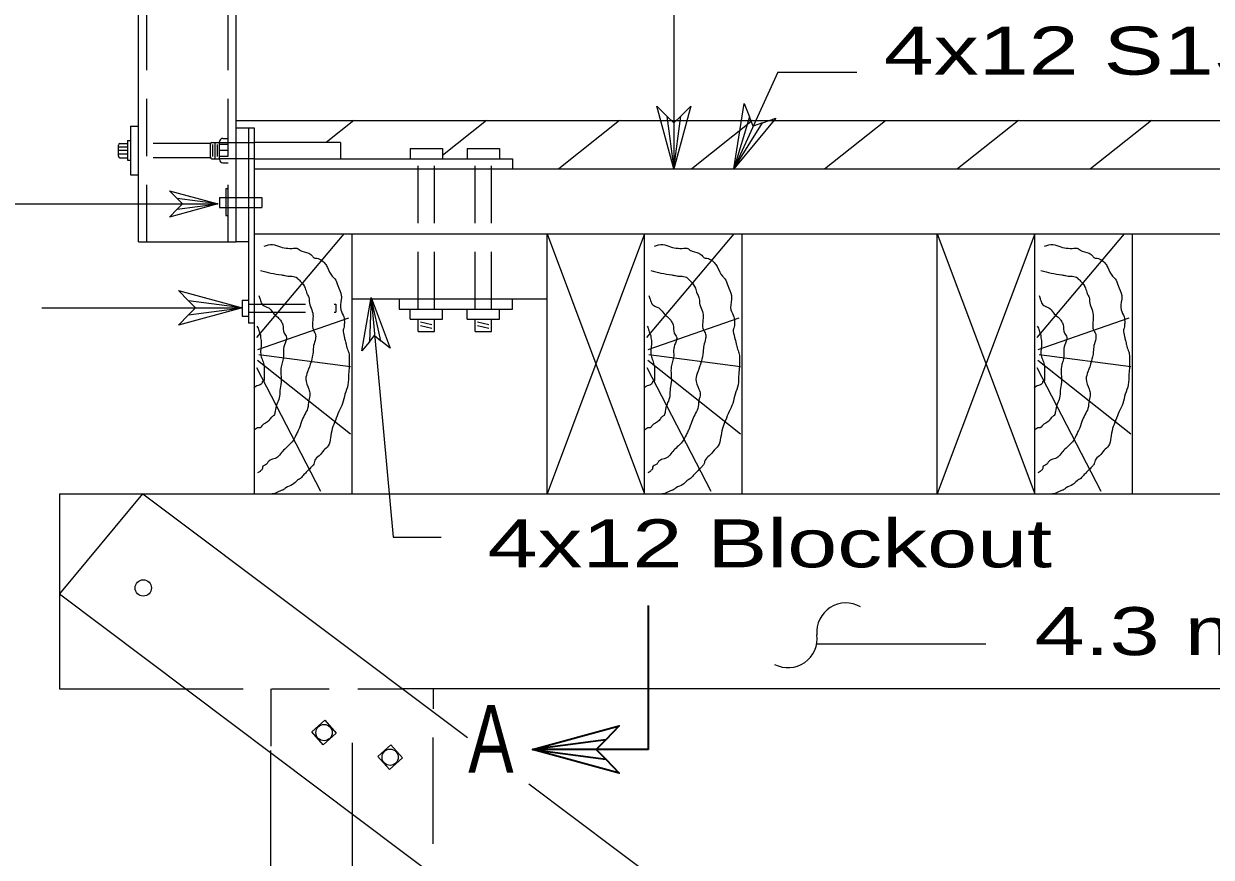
# Model space of a CAD drawing. Extents: x 13426 to 15509, y -9298 to -5111.
# Drawn here: x 15341.75 to 15374.08, y -5520.47 to -5497.78 of the extents above; entities that cross this region are included whole.
import ezdxf
from ezdxf.enums import TextEntityAlignment as Align

# ---------------------------------------------------------------- set-up
doc = ezdxf.new("R2010")
doc.units = 0
doc.header["$LTSCALE"] = 0.52
doc.linetypes.add('MEDIUM_DASHED', pattern=[4.5, 3, -1.5])
for name, color, linetype, lineweight in [('1', 7, 'Continuous', 13), ('15', 7, 'Continuous', 13), ('16', 7, 'Continuous', 25), ('2', 7, 'Continuous', 25), ('20', 7, 'Continuous', 13), ('4', 7, 'Continuous', 13), ('5', 7, 'Continuous', 25)]:
    doc.layers.add(name, color=color, linetype=linetype, lineweight=lineweight)
doc.layers.add('19', color=7, linetype='Continuous')

msp = doc.modelspace()

# ---------------------------------------------------------------- linework, layer by layer
at = {"layer": '1', "lineweight": 25}
for p, q in [((15342.717, -5510.579), (15342.717, -5515.89)), ((15342.717, -5515.89), (15346.162, -5515.89)), ((15417.071, -5515.89), (15352.058, -5515.89)), ((15352.897, -5515.89), (15352.897, -5516.435)), ((15352.897, -5520.11), (15352.897, -5517.212)), ((15348.471, -5573.164), (15348.471, -5517.564))]:
    msp.add_line(p, q, dxfattribs=at)
at = {"layer": '1', "linetype": 'MEDIUM_DASHED', "lineweight": 25}
for p, q in [((15346.162, -5515.89), (15352.058, -5515.89)), ((15348.471, -5515.89), (15348.471, -5517.564))]:
    msp.add_line(p, q, dxfattribs=at)
at = {"layer": '1', "lineweight": 25}
msp.add_lwpolyline([(15342.717, -5510.579), (15417.071, -5510.579), (15417.071, -5515.89)], dxfattribs=at)
at = {"layer": '15'}
for p, q in [((15359.445, -5491.991), (15359.445, -5501.728)), ((15362.274, -5499.093), (15361.077, -5501.728)), ((15362.274, -5499.093), (15364.424, -5499.093)), ((15341.243, -5502.683), (15347.034, -5502.683)), ((15342.24, -5505.514), (15347.695, -5505.51)), ((15363.336, -5514.659), (15367.935, -5514.659)), ((15350.684, -5517.363), (15350.684, -5528.112))]:
    msp.add_line(p, q, dxfattribs=at)
at = {"layer": '15', "lineweight": 35}
for q in [(15358.759, -5513.623), (15355.601, -5517.539)]:
    msp.add_line((15358.759, -5517.539), q, dxfattribs=at)
at = {"layer": '15'}
msp.add_lwpolyline([(15351.203, -5505.231), (15351.806, -5511.755), (15353.111, -5511.755)], dxfattribs=at)
for centre, start, end in [((15364.1313, -5514.3406), 59.84377, 185.31451), ((15362.5553, -5514.5196), 242.17771, 7.64844)]:
    msp.add_arc(centre, 0.7933, start, end, dxfattribs=at)
at = {"layer": '16'}
for points in [[(15359.633, -5500.289), (15359.91, -5500.024), (15359.445, -5501.728), (15358.98, -5500.024), (15359.257, -5500.289), (15359.445, -5501.728), (15359.633, -5500.289), (15359.445, -5500.477), (15359.257, -5500.289)], [(15361.857, -5500.473), (15362.225, -5500.344), (15361.077, -5501.728), (15361.364, -5499.952), (15361.508, -5500.315), (15361.077, -5501.728), (15361.857, -5500.473), (15361.603, -5500.568), (15361.508, -5500.315)], [(15345.921, -5502.537), (15345.715, -5502.323), (15347.034, -5502.683), (15345.715, -5503.042), (15345.921, -5502.828), (15347.034, -5502.683), (15345.921, -5502.537), (15346.066, -5502.683), (15345.921, -5502.828)], [(15346.23, -5505.32), (15345.96, -5505.038), (15347.695, -5505.51), (15345.961, -5505.984), (15346.231, -5505.703), (15347.695, -5505.51), (15346.23, -5505.32), (15346.422, -5505.511), (15346.231, -5505.703)], [(15351.157, -5506.438), (15350.948, -5506.68), (15351.203, -5505.231), (15351.72, -5506.609), (15351.469, -5506.41), (15351.203, -5505.231), (15351.157, -5506.438), (15351.299, -5506.268), (15351.469, -5506.41)]]:
    msp.add_lwpolyline(points, dxfattribs=at)
at = {"layer": '16', "lineweight": 35}
msp.add_lwpolyline([(15357.592, -5517.799), (15357.959, -5518.182), (15355.601, -5517.539), (15357.959, -5516.896), (15357.592, -5517.279), (15355.601, -5517.539), (15357.592, -5517.799), (15357.332, -5517.539), (15357.592, -5517.279)], dxfattribs=at)
at = {"layer": '2'}
for p, q in [((15352.266, -5501.174), (15353.151, -5501.174)), ((15352.266, -5501.174), (15352.266, -5501.451)), ((15353.151, -5501.174), (15353.151, -5501.451)), ((15353.815, -5501.174), (15354.7, -5501.174)), ((15353.815, -5501.174), (15353.815, -5501.451)), ((15354.7, -5501.174), (15354.7, -5501.451)), ((15347.246, -5502.267), (15347.246, -5502.998)), ((15347.246, -5502.267), (15347.303, -5502.267)), ((15347.074, -5502.511), (15347.074, -5502.781)), ((15347.074, -5502.511), (15347.241, -5502.511)), ((15347.074, -5502.781), (15347.241, -5502.781)), ((15347.246, -5502.998), (15347.303, -5502.998)), ((15347.695, -5505.301), (15347.862, -5505.301)), ((15347.695, -5505.301), (15347.695, -5505.744)), ((15352.266, -5505.821), (15352.266, -5505.545)), ((15353.151, -5505.821), (15353.151, -5505.545)), ((15353.815, -5505.821), (15353.815, -5505.545)), ((15354.7, -5505.821), (15354.7, -5505.545)), ((15347.695, -5505.744), (15347.862, -5505.744)), ((15352.266, -5505.821), (15353.151, -5505.821)), ((15352.487, -5506.153), (15352.487, -5505.821)), ((15352.55, -5505.992), (15352.858, -5506.069)), ((15352.552, -5505.89), (15352.86, -5505.966)), ((15352.93, -5506.153), (15352.93, -5505.821)), ((15353.815, -5505.821), (15354.7, -5505.821)), ((15354.036, -5506.153), (15354.036, -5505.821)), ((15354.099, -5505.992), (15354.407, -5506.069)), ((15354.101, -5505.89), (15354.409, -5505.966)), ((15354.479, -5506.153), (15354.479, -5505.821)), ((15352.487, -5506.153), (15352.93, -5506.153)), ((15354.036, -5506.153), (15354.479, -5506.153)), ((15344.983, -5510.579), (15342.719, -5513.305)), ((15344.986, -5510.579), (15353.824, -5517.216)), ((15342.719, -5513.305), (15414.878, -5567.491)), ((15355.496, -5518.472), (15417.071, -5564.711))]:
    msp.add_line(p, q, dxfattribs=at)
at = {"layer": '2', "linetype": 'MEDIUM_DASHED'}
for p, q in [((15352.487, -5505.545), (15352.487, -5501.451)), ((15352.93, -5505.545), (15352.93, -5501.451)), ((15354.036, -5505.545), (15354.036, -5501.451)), ((15354.479, -5505.545), (15354.479, -5501.451)), ((15347.241, -5502.511), (15348.226, -5502.511)), ((15347.241, -5502.781), (15348.226, -5502.781)), ((15348.226, -5502.511), (15348.226, -5502.781)), ((15347.862, -5505.633), (15350.241, -5505.633))]:
    msp.add_line(p, q, dxfattribs=at)
msp.add_lwpolyline([(15347.862, -5505.412), (15350.241, -5505.412), (15350.241, -5505.633)], dxfattribs=at)
at = {"layer": '2'}
for points in [[(15349.589, -5517.059), (15349.943, -5516.745), (15350.257, -5517.098), (15349.902, -5517.413)], [(15351.388, -5517.731), (15351.742, -5517.417), (15352.056, -5517.77), (15351.702, -5518.084)]]:
    msp.add_lwpolyline(points, close=True, dxfattribs=at)
for centre in [(15345.0015, -5513.1405), (15349.923, -5517.0797), (15351.7222, -5517.7512)]:
    msp.add_circle(centre, 0.2213, dxfattribs=at)
at = {"layer": '4', "lineweight": 25}
for p, q in [((15347.53, -5500.409), (15412.258, -5500.409)), ((15350.73, -5500.409), (15349.977, -5501.008)), ((15354.349, -5500.409), (15353.151, -5501.362)), ((15357.968, -5500.409), (15356.312, -5501.728)), ((15361.588, -5500.409), (15359.931, -5501.728)), ((15363.55, -5501.728), (15365.207, -5500.409)), ((15368.826, -5500.409), (15367.17, -5501.728)), ((15372.446, -5500.409), (15370.789, -5501.728)), ((15348.028, -5501.451), (15355.049, -5501.451)), ((15355.049, -5501.451), (15355.049, -5501.728)), ((15348.028, -5501.728), (15411.76, -5501.728)), ((15348.028, -5510.579), (15348.028, -5501.728)), ((15348.028, -5503.498), (15411.76, -5503.498)), ((15350.684, -5510.579), (15350.684, -5503.498)), ((15355.995, -5510.579), (15355.995, -5503.498)), ((15355.995, -5503.498), (15358.65, -5510.579)), ((15358.65, -5503.498), (15355.995, -5510.579)), ((15358.65, -5510.579), (15358.65, -5503.498)), ((15361.305, -5510.579), (15361.305, -5503.498)), ((15366.617, -5510.579), (15366.617, -5503.498)), ((15366.617, -5503.498), (15369.272, -5510.579)), ((15369.272, -5503.498), (15366.617, -5510.579)), ((15369.272, -5510.579), (15369.272, -5503.498)), ((15371.928, -5510.579), (15371.928, -5503.498)), ((15350.684, -5505.268), (15355.995, -5505.268)), ((15351.968, -5505.268), (15351.968, -5505.545)), ((15355.049, -5505.545), (15355.049, -5505.268)), ((15351.968, -5505.545), (15355.049, -5505.545))]:
    msp.add_line(p, q, dxfattribs=at)
at = {"layer": '4'}
for p, q in [((15344.653, -5500.567), (15344.875, -5500.567)), ((15344.653, -5500.567), (15344.653, -5501.895)), ((15344.323, -5501.38), (15344.323, -5501.081)), ((15344.571, -5501.134), (15344.323, -5501.134)), ((15344.367, -5501.037), (15344.571, -5501.037)), ((15344.571, -5500.954), (15344.571, -5501.495)), ((15344.571, -5500.954), (15344.653, -5500.954)), ((15346.828, -5501.407), (15346.828, -5501.052)), ((15346.872, -5501.008), (15347.077, -5501.008)), ((15346.889, -5501.064), (15346.889, -5501.395)), ((15346.953, -5501.008), (15346.953, -5501.451)), ((15347.016, -5501.064), (15347.016, -5501.395)), ((15347.077, -5501.472), (15347.077, -5500.987)), ((15347.309, -5501.064), (15347.077, -5501.064)), ((15347.166, -5500.898), (15347.309, -5500.898)), ((15350.368, -5501.008), (15348.028, -5501.008)), ((15350.368, -5501.008), (15350.368, -5501.451)), ((15344.571, -5501.231), (15344.323, -5501.231)), ((15344.571, -5501.328), (15344.323, -5501.328)), ((15344.367, -5501.425), (15344.571, -5501.425)), ((15344.571, -5501.495), (15344.653, -5501.495)), ((15346.872, -5501.451), (15347.077, -5501.451)), ((15347.309, -5501.229), (15347.077, -5501.229)), ((15347.309, -5501.395), (15347.077, -5501.395)), ((15347.166, -5501.56), (15347.309, -5501.56)), ((15344.653, -5501.895), (15344.875, -5501.895)), ((15350.459, -5503.497), (15348.081, -5506.317)), ((15361.081, -5503.497), (15358.702, -5506.317)), ((15371.703, -5503.497), (15369.325, -5506.317)), ((15350.59, -5505.79), (15348.113, -5506.657)), ((15361.212, -5505.79), (15358.735, -5506.657)), ((15371.834, -5505.79), (15369.357, -5506.657)), ((15350.639, -5508.951), (15348.113, -5506.946)), ((15350.639, -5507.116), (15348.146, -5506.793)), ((15361.262, -5508.951), (15358.735, -5506.946)), ((15361.262, -5507.116), (15358.768, -5506.793)), ((15371.884, -5508.951), (15369.357, -5506.946)), ((15371.884, -5507.116), (15369.39, -5506.793)), ((15349.836, -5510.514), (15348.097, -5507.15)), ((15360.458, -5510.514), (15358.719, -5507.15)), ((15371.08, -5510.514), (15369.341, -5507.15))]:
    msp.add_line(p, q, dxfattribs=at)
at = {"layer": '4', "linetype": 'MEDIUM_DASHED'}
for p, q in [((15346.83, -5501.037), (15344.571, -5501.037)), ((15347.077, -5501.008), (15348.028, -5501.008)), ((15346.83, -5501.425), (15344.571, -5501.425)), ((15348.028, -5501.451), (15347.077, -5501.451))]:
    msp.add_line(p, q, dxfattribs=at)
at = {"layer": '4'}
for centre, radius, start, end in [((15344.3669, -5501.0814), 0.0443, 90, 179.99999), ((15346.8718, -5501.0524), 0.0443, 90, 179.99999), ((15347.1659, -5500.987), 0.0885, 90, 179.99999), ((15344.3669, -5501.3801), 0.0443, 180, 269.99999), ((15346.8718, -5501.4065), 0.0443, 180, 269.99999), ((15347.1659, -5501.4719), 0.0885, 180, 269.99999)]:
    msp.add_arc(centre, radius, start, end, dxfattribs=at)
for points in [[(15348.294, -5503.837), (15348.523, -5503.786), (15348.737, -5503.854), (15349.147, -5503.888), (15349.18, -5503.888), (15349.262, -5503.939), (15349.508, -5504.024), (15349.606, -5504.108), (15349.672, -5504.159), (15349.688, -5504.159), (15349.951, -5504.312), (15350.016, -5504.414), (15350.148, -5504.652), (15350.213, -5504.72), (15350.295, -5504.907), (15350.393, -5505.179), (15350.393, -5505.281), (15350.377, -5505.57), (15350.459, -5505.756), (15350.475, -5505.926), (15350.459, -5506.062), (15350.442, -5506.113), (15350.442, -5506.164), (15350.459, -5506.232), (15350.475, -5506.317), (15350.508, -5506.436), (15350.525, -5506.521), (15350.574, -5506.674), (15350.607, -5506.81), (15350.607, -5506.929), (15350.607, -5507.116), (15350.59, -5507.32), (15350.574, -5507.608), (15350.492, -5507.863), (15350.426, -5508.118), (15350.328, -5508.339), (15350.23, -5508.577), (15350.148, -5508.798), (15350.098, -5509.052), (15350.033, -5509.273), (15349.917, -5509.392), (15349.787, -5509.545), (15349.672, -5509.664), (15349.655, -5509.732), (15349.623, -5509.8), (15349.557, -5509.868), (15349.458, -5509.97), (15349.376, -5510.055), (15349.278, -5510.157), (15349.18, -5510.225), (15349.065, -5510.327), (15348.884, -5510.412), (15348.819, -5510.463), (15348.737, -5510.497), (15348.655, -5510.53), (15348.507, -5510.582), (15348.506, -5510.582)], [(15358.916, -5503.837), (15359.145, -5503.786), (15359.359, -5503.854), (15359.769, -5503.888), (15359.802, -5503.888), (15359.884, -5503.939), (15360.129, -5504.024), (15360.228, -5504.108), (15360.294, -5504.159), (15360.31, -5504.159), (15360.572, -5504.312), (15360.638, -5504.414), (15360.769, -5504.652), (15360.835, -5504.72), (15360.917, -5504.907), (15361.015, -5505.179), (15361.015, -5505.281), (15360.999, -5505.57), (15361.081, -5505.756), (15361.097, -5505.926), (15361.081, -5506.062), (15361.065, -5506.113), (15361.065, -5506.164), (15361.081, -5506.232), (15361.097, -5506.317), (15361.13, -5506.436), (15361.147, -5506.521), (15361.196, -5506.674), (15361.229, -5506.81), (15361.229, -5506.929), (15361.229, -5507.116), (15361.212, -5507.32), (15361.196, -5507.608), (15361.114, -5507.863), (15361.048, -5508.118), (15360.95, -5508.339), (15360.851, -5508.577), (15360.769, -5508.798), (15360.72, -5509.052), (15360.654, -5509.273), (15360.54, -5509.392), (15360.408, -5509.545), (15360.294, -5509.664), (15360.277, -5509.732), (15360.244, -5509.8), (15360.179, -5509.868), (15360.081, -5509.97), (15359.999, -5510.055), (15359.9, -5510.157), (15359.802, -5510.225), (15359.687, -5510.327), (15359.506, -5510.412), (15359.441, -5510.463), (15359.359, -5510.497), (15359.277, -5510.53), (15359.129, -5510.582), (15359.128, -5510.582)], [(15369.538, -5503.837), (15369.768, -5503.786), (15369.98, -5503.854), (15370.391, -5503.888), (15370.423, -5503.888), (15370.506, -5503.939), (15370.752, -5504.024), (15370.85, -5504.108), (15370.916, -5504.159), (15370.932, -5504.159), (15371.195, -5504.312), (15371.26, -5504.414), (15371.391, -5504.652), (15371.457, -5504.72), (15371.539, -5504.907), (15371.638, -5505.179), (15371.638, -5505.281), (15371.621, -5505.57), (15371.703, -5505.756), (15371.72, -5505.926), (15371.703, -5506.062), (15371.687, -5506.113), (15371.687, -5506.164), (15371.703, -5506.232), (15371.72, -5506.317), (15371.752, -5506.436), (15371.768, -5506.521), (15371.818, -5506.674), (15371.85, -5506.81), (15371.85, -5506.929), (15371.85, -5507.116), (15371.834, -5507.32), (15371.818, -5507.608), (15371.736, -5507.863), (15371.67, -5508.118), (15371.572, -5508.339), (15371.473, -5508.577), (15371.391, -5508.798), (15371.342, -5509.052), (15371.277, -5509.273), (15371.162, -5509.392), (15371.031, -5509.545), (15370.916, -5509.664), (15370.899, -5509.732), (15370.866, -5509.8), (15370.801, -5509.868), (15370.702, -5509.97), (15370.62, -5510.055), (15370.522, -5510.157), (15370.423, -5510.225), (15370.309, -5510.327), (15370.128, -5510.412), (15370.063, -5510.463), (15369.98, -5510.497), (15369.898, -5510.53), (15369.751, -5510.582), (15369.75, -5510.582)], [(15348.195, -5504.499), (15348.474, -5504.567), (15348.769, -5504.618), (15348.868, -5504.635), (15348.999, -5504.652), (15349.048, -5504.652), (15349.196, -5504.703), (15349.212, -5504.72), (15349.294, -5504.805), (15349.409, -5504.975), (15349.458, -5505.128), (15349.508, -5505.23), (15349.524, -5505.383), (15349.59, -5505.57), (15349.623, -5505.739), (15349.606, -5505.96), (15349.623, -5506.096), (15349.688, -5506.232), (15349.688, -5506.351), (15349.639, -5506.538), (15349.623, -5506.708), (15349.475, -5507.251), (15349.426, -5507.455), (15349.508, -5507.727), (15349.54, -5507.863), (15349.508, -5508.033), (15349.475, -5508.254), (15349.393, -5508.424), (15349.311, -5508.611), (15349.229, -5508.832), (15349.18, -5508.933), (15349.081, -5509.121), (15348.95, -5509.273), (15348.819, -5509.392), (15348.589, -5509.613), (15348.523, -5509.63), (15348.458, -5509.664), (15348.408, -5509.698), (15348.359, -5509.766), (15348.244, -5509.851), (15348.244, -5509.885), (15348.195, -5509.953), (15348.179, -5509.97), (15348.113, -5510.004)], [(15358.817, -5504.499), (15359.096, -5504.567), (15359.391, -5504.618), (15359.49, -5504.635), (15359.621, -5504.652), (15359.67, -5504.652), (15359.818, -5504.703), (15359.834, -5504.72), (15359.917, -5504.805), (15360.031, -5504.975), (15360.081, -5505.128), (15360.129, -5505.23), (15360.146, -5505.383), (15360.212, -5505.57), (15360.244, -5505.739), (15360.228, -5505.96), (15360.244, -5506.096), (15360.31, -5506.232), (15360.31, -5506.351), (15360.261, -5506.538), (15360.244, -5506.708), (15360.097, -5507.251), (15360.047, -5507.455), (15360.129, -5507.727), (15360.162, -5507.863), (15360.129, -5508.033), (15360.097, -5508.254), (15360.015, -5508.424), (15359.933, -5508.611), (15359.851, -5508.832), (15359.802, -5508.933), (15359.703, -5509.121), (15359.572, -5509.273), (15359.441, -5509.392), (15359.211, -5509.613), (15359.145, -5509.63), (15359.08, -5509.664), (15359.031, -5509.698), (15358.981, -5509.766), (15358.867, -5509.851), (15358.867, -5509.885), (15358.817, -5509.953), (15358.801, -5509.97), (15358.735, -5510.004)], [(15369.439, -5504.499), (15369.718, -5504.567), (15370.013, -5504.618), (15370.112, -5504.635), (15370.243, -5504.652), (15370.292, -5504.652), (15370.44, -5504.703), (15370.456, -5504.72), (15370.538, -5504.805), (15370.653, -5504.975), (15370.702, -5505.128), (15370.752, -5505.23), (15370.768, -5505.383), (15370.834, -5505.57), (15370.866, -5505.739), (15370.85, -5505.96), (15370.866, -5506.096), (15370.932, -5506.232), (15370.932, -5506.351), (15370.883, -5506.538), (15370.866, -5506.708), (15370.719, -5507.251), (15370.67, -5507.455), (15370.752, -5507.727), (15370.784, -5507.863), (15370.752, -5508.033), (15370.719, -5508.254), (15370.637, -5508.424), (15370.555, -5508.611), (15370.473, -5508.832), (15370.423, -5508.933), (15370.325, -5509.121), (15370.194, -5509.273), (15370.063, -5509.392), (15369.833, -5509.613), (15369.768, -5509.63), (15369.702, -5509.664), (15369.653, -5509.698), (15369.604, -5509.766), (15369.489, -5509.851), (15369.489, -5509.885), (15369.439, -5509.953), (15369.423, -5509.97), (15369.357, -5510.004)], [(15348.146, -5505.179), (15348.179, -5505.281), (15348.228, -5505.4), (15348.343, -5505.485), (15348.392, -5505.502), (15348.474, -5505.57), (15348.589, -5505.705), (15348.687, -5505.79), (15348.753, -5505.875), (15348.802, -5505.978), (15348.835, -5506.198), (15348.901, -5506.317), (15348.884, -5506.419), (15348.819, -5506.623), (15348.819, -5506.827), (15348.753, -5507.116), (15348.753, -5507.541), (15348.72, -5507.761), (15348.704, -5507.965), (15348.638, -5508.135), (15348.589, -5508.339), (15348.556, -5508.441), (15348.49, -5508.492), (15348.425, -5508.577), (15348.228, -5508.73), (15348.179, -5508.781), (15348.146, -5508.781), (15348.031, -5508.832)], [(15358.768, -5505.179), (15358.801, -5505.281), (15358.85, -5505.4), (15358.965, -5505.485), (15359.014, -5505.502), (15359.096, -5505.57), (15359.211, -5505.705), (15359.309, -5505.79), (15359.375, -5505.875), (15359.424, -5505.978), (15359.457, -5506.198), (15359.523, -5506.317), (15359.506, -5506.419), (15359.441, -5506.623), (15359.441, -5506.827), (15359.375, -5507.116), (15359.375, -5507.541), (15359.342, -5507.761), (15359.326, -5507.965), (15359.26, -5508.135), (15359.211, -5508.339), (15359.178, -5508.441), (15359.113, -5508.492), (15359.047, -5508.577), (15358.85, -5508.73), (15358.801, -5508.781), (15358.768, -5508.781), (15358.653, -5508.832)], [(15369.39, -5505.179), (15369.423, -5505.281), (15369.472, -5505.4), (15369.587, -5505.485), (15369.636, -5505.502), (15369.718, -5505.57), (15369.833, -5505.705), (15369.932, -5505.79), (15369.997, -5505.875), (15370.046, -5505.978), (15370.079, -5506.198), (15370.145, -5506.317), (15370.128, -5506.419), (15370.063, -5506.623), (15370.063, -5506.827), (15369.997, -5507.116), (15369.997, -5507.541), (15369.964, -5507.761), (15369.948, -5507.965), (15369.882, -5508.135), (15369.833, -5508.339), (15369.8, -5508.441), (15369.735, -5508.492), (15369.669, -5508.577), (15369.472, -5508.73), (15369.423, -5508.781), (15369.39, -5508.781), (15369.275, -5508.832)], [(15348.097, -5506.011), (15348.146, -5506.13), (15348.162, -5506.198), (15348.195, -5506.266), (15348.195, -5506.334), (15348.212, -5506.402), (15348.212, -5506.453), (15348.212, -5506.521), (15348.195, -5506.691), (15348.212, -5506.844), (15348.261, -5506.98), (15348.294, -5507.132), (15348.294, -5507.439), (15348.278, -5507.506), (15348.261, -5507.506), (15348.228, -5507.574), (15348.129, -5507.625), (15348.064, -5507.659), (15348.015, -5507.693)], [(15358.719, -5506.011), (15358.768, -5506.13), (15358.784, -5506.198), (15358.817, -5506.266), (15358.817, -5506.334), (15358.834, -5506.402), (15358.834, -5506.453), (15358.834, -5506.521), (15358.817, -5506.691), (15358.834, -5506.844), (15358.883, -5506.98), (15358.916, -5507.132), (15358.916, -5507.439), (15358.899, -5507.506), (15358.883, -5507.506), (15358.85, -5507.574), (15358.752, -5507.625), (15358.686, -5507.659), (15358.637, -5507.693)], [(15369.341, -5506.011), (15369.39, -5506.13), (15369.407, -5506.198), (15369.439, -5506.266), (15369.439, -5506.334), (15369.456, -5506.402), (15369.456, -5506.453), (15369.456, -5506.521), (15369.439, -5506.691), (15369.456, -5506.844), (15369.505, -5506.98), (15369.538, -5507.132), (15369.538, -5507.439), (15369.521, -5507.506), (15369.505, -5507.506), (15369.472, -5507.574), (15369.374, -5507.625), (15369.308, -5507.659), (15369.259, -5507.693)]]:
    msp.add_spline(points, degree=3, dxfattribs=at)
at = {"layer": '5', "linetype": 'MEDIUM_DASHED'}
for p, q in [((15345.096, -5503.719), (15345.096, -5487.122)), ((15347.309, -5503.719), (15347.309, -5487.122))]:
    msp.add_line(p, q, dxfattribs=at)
at = {"layer": '5'}
for p, q in [((15347.862, -5500.621), (15347.862, -5505.932)), ((15348.028, -5501.728), (15348.028, -5500.621)), ((15344.875, -5503.719), (15347.53, -5503.719)), ((15348.028, -5505.932), (15347.862, -5505.932))]:
    msp.add_line(p, q, dxfattribs=at)
for points in [[(15344.875, -5503.719), (15344.875, -5487.122), (15347.53, -5487.122)], [(15347.862, -5503.719), (15347.53, -5503.719), (15347.53, -5487.122)], [(15348.028, -5500.621), (15347.862, -5500.621), (15347.53, -5500.621)]]:
    msp.add_lwpolyline(points, dxfattribs=at)

# ---------------------------------------------------------------- texts
at = {"layer": '19', "width": 1.4}
msp.add_text('4.3 m 10x12 Cap S1E', height=1.307, dxfattribs=at).set_placement((15369.27, -5514.971))
at = {"layer": '20', "width": 1.4}
for s, p in [('4x12 S1S Plank deck', (15365.161, -5499.163)), ('4x12 Blockout', (15354.372, -5512.58))]:
    msp.add_text(s, height=1.307, dxfattribs=at).set_placement(p)
at = {"layer": '20', "width": 0.75}
msp.add_text('A', height=1.844, dxfattribs=at).set_placement((15354.466, -5518.169), align=Align.CENTER)

doc.saveas('drawing.dxf')
